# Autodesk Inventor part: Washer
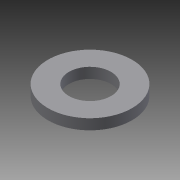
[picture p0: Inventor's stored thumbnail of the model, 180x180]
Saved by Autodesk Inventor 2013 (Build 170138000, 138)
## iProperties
Created: 2004-07
Part Number: Washer
Document SubType Name: Modeling
Designer: Autodesk, Inc.
Manufacturer: Standard
Standards Organization: Custom
Density: 1 g/cm^3
Mass: 2.41274 g
Surface Area: 18.0956 cm^2
Volume: 2.41274 cm^3
Material: Generic
Author: Autodesk, Inc.
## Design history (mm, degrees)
sketch "Sketch1"
  geometry: C1 r 16 at (0, 0); C2 r 8 at (0, 0)
  constraints: 2 centre point, 1 coincident
  dimensions: "d0" = 32 diameter of C1; "d1" = 16 diameter of C2
extrude "Extrusion1" new body sketch "Sketch1" distance "d2" = 4; taper "d3" = 0 deg
body "Solid1"
